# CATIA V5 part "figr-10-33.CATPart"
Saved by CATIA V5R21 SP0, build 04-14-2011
Part number: Part1
Bounding box of the stored display mesh (mm): x 0 to 100, y -43.492 to 31.468, z -3.623 to 11.497
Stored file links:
  D:\CATIA V5R21 E-RESOURCES\CATIA-V5R21\catia-v5r21-prt\c10-catia-v5r20-prt\c10-catia-v5r21-figr-10-33.CATPart
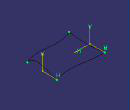
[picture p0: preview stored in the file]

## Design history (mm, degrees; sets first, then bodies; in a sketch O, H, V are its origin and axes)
Set1
  Sketch1 on yz-plane, origin (0, 0, 0), H (0, 1, 0), V (0, 0, 1)
  Plane1: type Offset, RefPlane yz-plane, Offset 100
  Sketch2 on xy-plane, origin (0, 0, 0), H (1, 0, 0), V (0, 1, 0)
    spline S1 through (0, 31.0443) (19.7053, 31.0443) (51.809, 26.4574) (100, 31.0443)
    reference intersected line E1 through (100, 0) direction (0, 1) from Plane1
    point P1 (0, 31.0443)
    point P2 (100, 31.0443)
    coincidence: P1 V, P2 E1
  Sketch3 on xy-plane, origin (0, 0, 0), H (1, 0, 0), V (0, 1, 0)
    spline S1 through (0, -43.492) (26.209, -36.2295) (80.3728, -38.1407) (100, -32.0249)
    reference intersected line E1 through (100, 0) direction (0, 1) from Plane1
    point P1 (0, -43.492)
    point P2 (100, -32.0249)
    coincidence: P1 V, P2 E1
  Sketch4 on Plane1, origin (100, 0, 0), H (0, 1, 0), V (0, 0, 1)
    spline S1 through (-32.0249, 0) (-14.5305, 11.3827) (11.9668, 5.3652) (31.0443, 0)
    reference projected point E1 (31.0443, 0) from vertex of Sketch2
    reference projected point E2 (-32.0249, 0) from vertex of Sketch3
    point P1 (-32.0249, 0)
    point P2 (31.0443, 0)
    coincidence: P1 H, P2 H, P2 E1, P1 E2
  Sketch5 on yz-plane, origin (0, 0, 0), H (0, 1, 0), V (0, 0, 1)
    spline S1 through (31.0443, 0) (7.4727, -3.1675) (-43.492, 0)
    reference projected point E1 (-43.492, 0) from vertex of Sketch3
    reference projected point E2 (31.0443, 0) from vertex of Sketch2
    point P1 (31.0443, 0)
    point P2 (-43.492, 0)
    coincidence: P1 H, P2 H, P2 E1, P1 E2
Body1 (main body)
